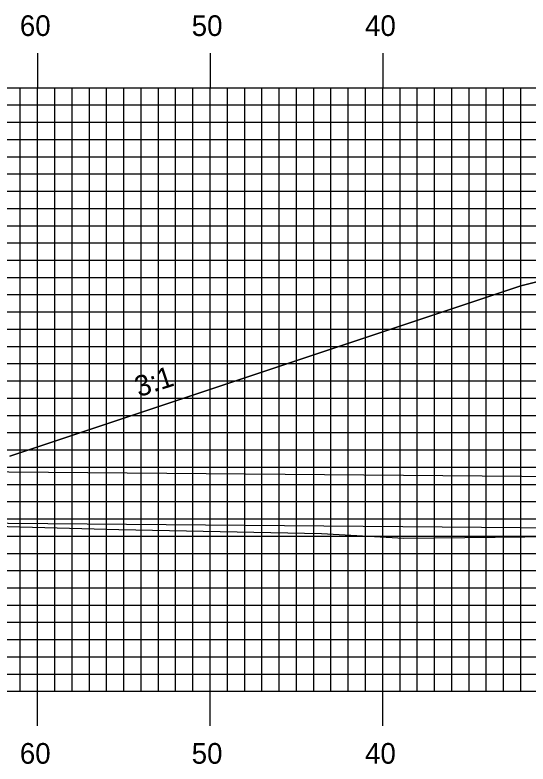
# Model space of a CAD drawing. Extents: x 1781467 to 1781810, y 442591 to 442811.
# Drawn here: x 1781571.1 to 1781600.82, y 442659.45 to 442702.88 of the extents above; entities that cross this region are included whole.
import ezdxf

# ---------------------------------------------------------------- set-up
doc = ezdxf.new("R2010")
doc.units = 0
for name, color, linetype in [('ANNOTATION', 7, 'Continuous'), ('D_Drainage_Culvert', 7, 'Continuous'), ('D_Roadway_Centerline', 7, 'Continuous'), ('D_Roadway_SlopeLines', 7, 'Continuous'), ('H_V ANNOTATION', 7, 'Continuous'), ('MAJOR', 7, 'Continuous'), ('MINOR', 7, 'Continuous'), ('S_Roadway_Centerline', 7, 'Continuous')]:
    doc.layers.add(name, color=color, linetype=linetype)

msp = doc.modelspace()

# ---------------------------------------------------------------- linework, layer by layer
at = {"layer": 'D_Drainage_Culvert'}
msp.add_lwpolyline([(1781561.558, 442673.475), (1781561.583, 442676.475), (1781705.578, 442675.25), (1781705.553, 442672.25)], close=True, dxfattribs=at)
at = {"layer": 'D_Roadway_Centerline'}
msp.add_lwpolyline([(1781570.792, 442677.306), (1781600.408, 442687.178), (1781602.234, 442687.634), (1781612.408, 442690.178), (1781620.408, 442690.498), (1781632.408, 442690.738), (1781644.408, 442690.498), (1781652.408, 442690.178), (1781662.582, 442687.634), (1781664.408, 442687.178), (1781697.344, 442676.199)], dxfattribs=at)
at = {"layer": 'D_Roadway_SlopeLines'}
msp.add_lwpolyline([(1781612.408, 442690.178), (1781600.408, 442687.178), (1781570.792, 442677.306)], dxfattribs=at)
at = {"layer": 'MAJOR'}
for p, q in [((1781572.408, 442700.669), (1781572.408, 442698.665)), ((1781582.408, 442700.669), (1781582.408, 442698.665)), ((1781592.408, 442700.669), (1781592.408, 442698.665)), ((1781492.408, 442698.665), (1781772.408, 442698.665)), ((1781492.408, 442698.665), (1781772.408, 442698.665)), ((1781572.408, 442663.665), (1781572.408, 442698.665)), ((1781582.408, 442663.665), (1781582.408, 442698.665)), ((1781592.408, 442663.665), (1781592.408, 442698.665)), ((1781492.408, 442693.665), (1781772.408, 442693.665)), ((1781492.408, 442688.665), (1781772.408, 442688.665)), ((1781492.408, 442683.665), (1781772.408, 442683.665)), ((1781492.408, 442678.665), (1781772.408, 442678.665)), ((1781492.408, 442673.665), (1781772.408, 442673.665)), ((1781492.408, 442668.665), (1781772.408, 442668.665)), ((1781492.408, 442663.665), (1781772.408, 442663.665)), ((1781492.408, 442663.665), (1781772.408, 442663.665)), ((1781572.408, 442661.661), (1781572.408, 442663.665)), ((1781582.408, 442661.661), (1781582.408, 442663.665)), ((1781592.408, 442661.661), (1781592.408, 442663.665))]:
    msp.add_line(p, q, dxfattribs=at)
at = {"layer": 'MINOR'}
for p, q in [((1781571.408, 442663.665), (1781571.408, 442698.665)), ((1781573.408, 442663.665), (1781573.408, 442698.665)), ((1781574.408, 442663.665), (1781574.408, 442698.665)), ((1781575.408, 442663.665), (1781575.408, 442698.665)), ((1781576.408, 442663.665), (1781576.408, 442698.665)), ((1781577.408, 442663.665), (1781577.408, 442698.665)), ((1781578.408, 442663.665), (1781578.408, 442698.665)), ((1781579.408, 442663.665), (1781579.408, 442698.665)), ((1781580.408, 442663.665), (1781580.408, 442698.665)), ((1781581.408, 442663.665), (1781581.408, 442698.665)), ((1781583.408, 442663.665), (1781583.408, 442698.665)), ((1781584.408, 442663.665), (1781584.408, 442698.665)), ((1781585.408, 442663.665), (1781585.408, 442698.665)), ((1781586.408, 442663.665), (1781586.408, 442698.665)), ((1781587.408, 442663.665), (1781587.408, 442698.665)), ((1781588.408, 442663.665), (1781588.408, 442698.665)), ((1781589.408, 442663.665), (1781589.408, 442698.665)), ((1781590.408, 442663.665), (1781590.408, 442698.665)), ((1781591.408, 442663.665), (1781591.408, 442698.665)), ((1781593.408, 442663.665), (1781593.408, 442698.665)), ((1781594.408, 442663.665), (1781594.408, 442698.665)), ((1781595.408, 442663.665), (1781595.408, 442698.665)), ((1781596.408, 442663.665), (1781596.408, 442698.665)), ((1781597.408, 442663.665), (1781597.408, 442698.665)), ((1781598.408, 442663.665), (1781598.408, 442698.665)), ((1781599.408, 442663.665), (1781599.408, 442698.665)), ((1781600.408, 442663.665), (1781600.408, 442698.665)), ((1781492.408, 442697.665), (1781772.408, 442697.665)), ((1781492.408, 442696.665), (1781772.408, 442696.665)), ((1781492.408, 442695.665), (1781772.408, 442695.665)), ((1781492.408, 442694.665), (1781772.408, 442694.665)), ((1781492.408, 442692.665), (1781772.408, 442692.665)), ((1781492.408, 442691.665), (1781772.408, 442691.665)), ((1781492.408, 442690.665), (1781772.408, 442690.665)), ((1781492.408, 442689.665), (1781772.408, 442689.665)), ((1781492.408, 442687.665), (1781772.408, 442687.665)), ((1781492.408, 442686.665), (1781772.408, 442686.665)), ((1781492.408, 442685.665), (1781772.408, 442685.665)), ((1781492.408, 442684.665), (1781772.408, 442684.665)), ((1781492.408, 442682.665), (1781772.408, 442682.665)), ((1781492.408, 442681.665), (1781772.408, 442681.665)), ((1781492.408, 442680.665), (1781772.408, 442680.665)), ((1781492.408, 442679.665), (1781772.408, 442679.665)), ((1781492.408, 442677.665), (1781772.408, 442677.665)), ((1781492.408, 442676.665), (1781772.408, 442676.665)), ((1781492.408, 442675.665), (1781772.408, 442675.665)), ((1781492.408, 442674.665), (1781772.408, 442674.665)), ((1781492.408, 442672.665), (1781772.408, 442672.665)), ((1781492.408, 442671.665), (1781772.408, 442671.665)), ((1781492.408, 442670.665), (1781772.408, 442670.665)), ((1781492.408, 442669.665), (1781772.408, 442669.665)), ((1781492.408, 442667.665), (1781772.408, 442667.665)), ((1781492.408, 442666.665), (1781772.408, 442666.665)), ((1781492.408, 442665.665), (1781772.408, 442665.665)), ((1781492.408, 442664.665), (1781772.408, 442664.665))]:
    msp.add_line(p, q, dxfattribs=at)
at = {"layer": 'S_Roadway_Centerline'}
msp.add_lwpolyline([(1781492.408, 442676.385), (1781508.31, 442675.463), (1781512.714, 442675.229), (1781517.267, 442674.997), (1781532.006, 442674.445), (1781541.391, 442674.084), (1781554.263, 442673.537), (1781559.209, 442673.54), (1781577.11, 442673.042), (1781588.859, 442672.808), (1781593.637, 442672.549), (1781598.923, 442672.598), (1781605.769, 442672.682)], dxfattribs=at)

# ---------------------------------------------------------------- texts
at = {"layer": 'ANNOTATION'}
msp.add_text('3:1', height=1.2, rotation=18.4348, dxfattribs=at).set_placement((1781578.279, 442680.71))
at = {"layer": 'H_V ANNOTATION'}
for s, p in [('60', (1781571.38, 442701.665)), ('50', (1781581.337, 442701.665)), ('40', (1781591.38, 442701.665)), ('60', (1781571.38, 442659.465)), ('50', (1781581.337, 442659.465)), ('40', (1781591.38, 442659.465))]:
    msp.add_text(s, height=1.2, dxfattribs=at).set_placement(p)

doc.saveas('drawing.dxf')
